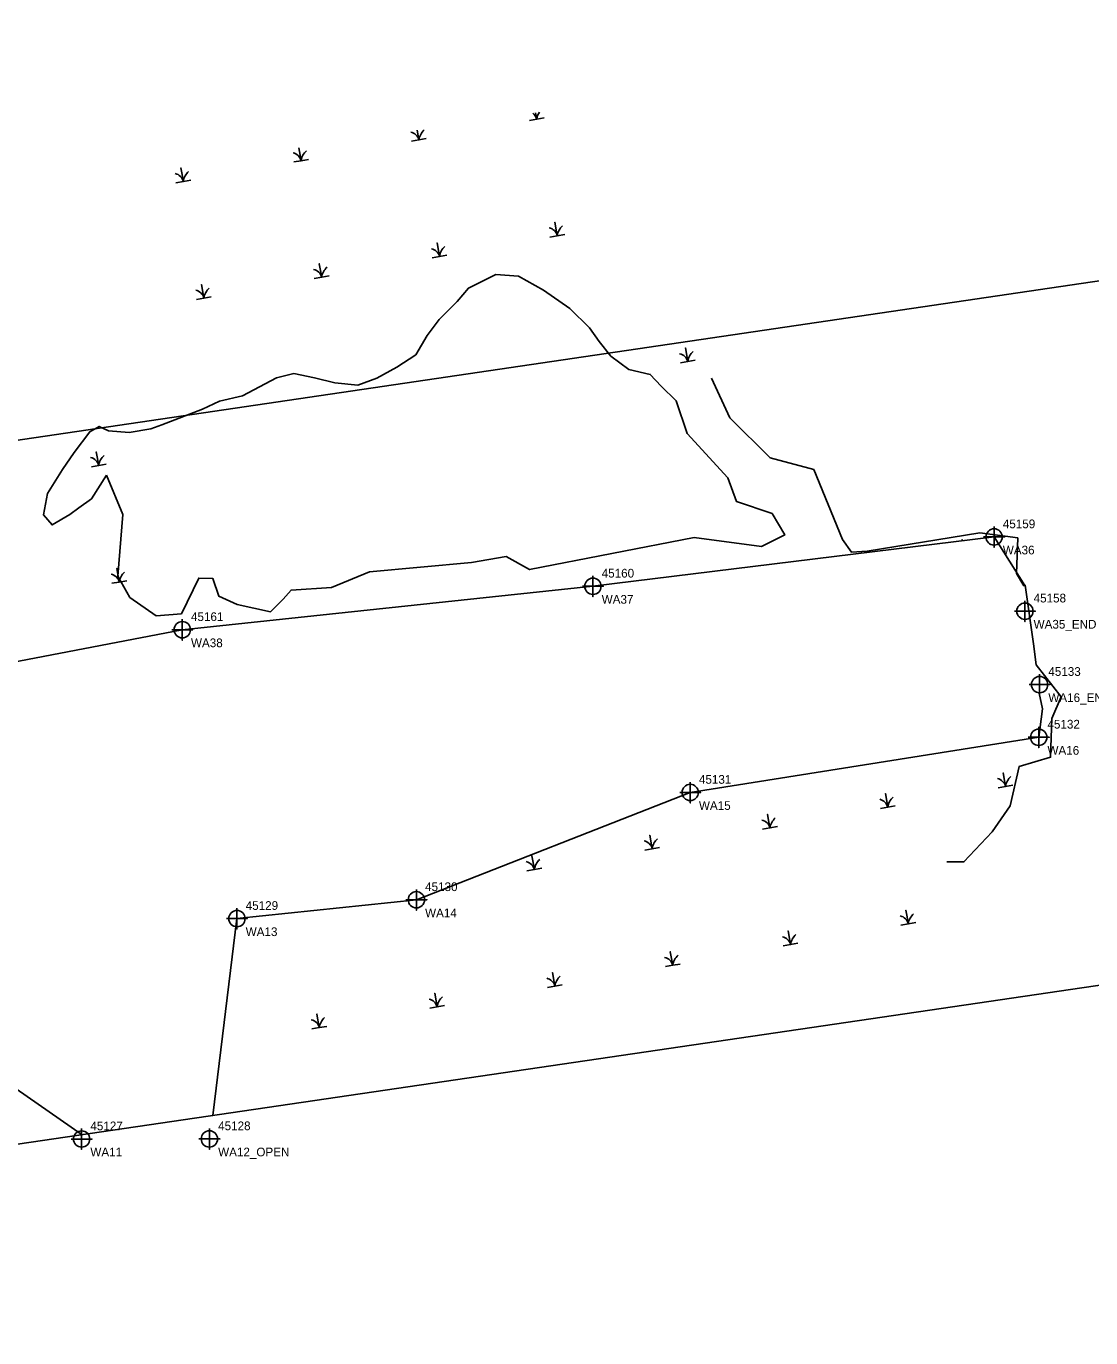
# Model space of a CAD drawing. Extents: x 2111078 to 2112839, y 581517 to 581907.
# Drawn here: x 2111765.7 to 2112071, y 581523.2 to 581899.2 of the extents above; entities that cross this region are included whole.
import ezdxf

# ---------------------------------------------------------------- set-up
doc = ezdxf.new("R2010")
doc.units = 0
for name, color, linetype in [('Default', 7, 'Continuous'), ('Exist Environmental Wetland Boundary', 7, 'Continuous'), ('Exist Environmental Wetland Boundary Cogo Comment', 7, 'Continuous'), ('Exist Environmental Wetland Boundary Cogo Number', 7, 'Continuous'), ('Exist Environmental Wetland Boundary Cogo Point CELL', 7, 'Continuous'), ('Exist Hydro Jurisdictional Stream or Body of Water Mitigable', 7, 'Continuous'), ('Exist Hydro Jurisdictional Stream or Body of Water NEU NonMitigable', 7, 'Continuous'), ('Exist Hydro Swamp or Marsh', 7, 'Continuous')]:
    doc.layers.add(name, color=color, linetype=linetype)

msp = doc.modelspace()

# ---------------------------------------------------------------- linework, layer by layer
at = {"layer": 'Default'}
msp.add_lwpolyline([(2111089.87, 581523.16), (2111077.52, 581722.78), (2111579.66, 581753.48), (2112568.99, 581899.18), (2112598.13, 581701.32), (2111600.4, 581554.74), (2111516.52, 581549.55)], close=True, dxfattribs=at)
at = {"layer": 'Exist Environmental Wetland Boundary'}
for points in [[(2112052.09, 581738.85), (2112043.26, 581752.76), (2111928.23, 581738.62), (2111810.46, 581726.15), (2111700.26, 581705.05), (2111584.01, 581692.46), (2111561.53, 581686.62), (2111561.94, 581674.72), (2111567.72, 581661.99), (2111570.98, 581641.26), (2111577.49, 581632.74), (2111580.7, 581632.54), (2111595.75, 581624.66), (2111698.44, 581639.38), (2111781.79, 581581.39)], [(2111819.27, 581586.89), (2111826.15, 581643.33), (2111877.59, 581648.73), (2111956.11, 581679.5), (2112056.05, 581695.32), (2112057.1, 581703.46), (2112056.2, 581707.94)]]:
    msp.add_lwpolyline(points, dxfattribs=at)
at = {"layer": 'Exist Environmental Wetland Boundary Cogo Point CELL'}
for points in [[(2112043.25, 581755.76), (2112043.25, 581749.76), (2112043.25, 581752.76), (2112046.25, 581752.76), (2112040.25, 581752.76)], [(2111928.23, 581741.62), (2111928.23, 581735.62), (2111928.23, 581738.62), (2111931.23, 581738.62), (2111925.23, 581738.62)], [(2112052.08, 581734.48), (2112052.08, 581728.48), (2112052.08, 581731.48), (2112055.08, 581731.48), (2112049.08, 581731.48)], [(2111810.46, 581729.15), (2111810.46, 581723.15), (2111810.46, 581726.15), (2111813.46, 581726.15), (2111807.46, 581726.15)], [(2112056.3, 581713.43), (2112056.3, 581707.43), (2112056.3, 581710.43), (2112059.3, 581710.43), (2112053.3, 581710.43)], [(2112056.05, 581698.32), (2112056.05, 581692.32), (2112056.05, 581695.32), (2112059.05, 581695.32), (2112053.05, 581695.32)], [(2111956.11, 581682.5), (2111956.11, 581676.5), (2111956.11, 581679.5), (2111959.11, 581679.5), (2111953.11, 581679.5)], [(2111877.59, 581651.73), (2111877.59, 581645.73), (2111877.59, 581648.73), (2111880.59, 581648.73), (2111874.59, 581648.73)], [(2111826.15, 581646.33), (2111826.15, 581640.33), (2111826.15, 581643.33), (2111829.15, 581643.33), (2111823.15, 581643.33)], [(2111781.61, 581583.15), (2111781.61, 581577.15), (2111781.61, 581580.15), (2111784.61, 581580.15), (2111778.61, 581580.15)], [(2111818.25, 581583.17), (2111818.25, 581577.17), (2111818.25, 581580.17), (2111821.25, 581580.17), (2111815.25, 581580.17)]]:
    msp.add_lwpolyline(points, dxfattribs=at)
for centre in [(2112043.25, 581752.76), (2111928.23, 581738.62), (2112052.08, 581731.48), (2111810.46, 581726.15), (2112056.3, 581710.43), (2112056.05, 581695.32), (2111956.11, 581679.5), (2111877.59, 581648.73), (2111826.15, 581643.33), (2111781.61, 581580.15), (2111818.25, 581580.17)]:
    msp.add_circle(centre, 2.34, dxfattribs=at)
at = {"layer": 'Exist Hydro Jurisdictional Stream or Body of Water Mitigable'}
for points in [[(2112059.84, 581700.7), (2112062.49, 581706.94), (2112055.34, 581716.13), (2112054.57, 581722.13), (2112052.17, 581738.93), (2112051.74, 581738.78), (2112049.7, 581742.29), (2112050.01, 581752.49), (2112039.14, 581753.92), (2112006.88, 581748.64), (2112002.32, 581748.44), (2111999.78, 581752.01), (2111991.54, 581772.1), (2111979.08, 581775.41), (2111967.43, 581786.95), (2111962.18, 581798.24)], [(2112029.69, 581659.66), (2112034.58, 581659.59), (2112042.72, 581668.18), (2112047.85, 581675.67), (2112050.4, 581686.92), (2112059.44, 581689.6), (2112059.84, 581700.7)]]:
    msp.add_lwpolyline(points, dxfattribs=at)
at = {"layer": 'Exist Hydro Jurisdictional Stream or Body of Water NEU NonMitigable'}
for points in [[(2111816.23, 581789.37), (2111821.14, 581791.65), (2111827.77, 581793.26), (2111837.5, 581798.42), (2111842.46, 581799.58), (2111848.36, 581798.34), (2111854.22, 581796.98), (2111860.81, 581796.24), (2111866.24, 581798.28), (2111871.96, 581801.48), (2111877.4, 581804.97), (2111880.65, 581810.55), (2111884.17, 581815.14), (2111889.33, 581820.24), (2111892.5, 581824.1), (2111900.42, 581828.05), (2111906.87, 581827.5), (2111914.07, 581823.55), (2111921.55, 581818.23), (2111927.23, 581812.73), (2111930.01, 581808.77), (2111933.39, 581804.55), (2111938.54, 581800.77), (2111944.65, 581799.37), (2111947.77, 581795.96), (2111952.05, 581791.74)], [(2111979.61, 581759.45), (2111969.35, 581762.93), (2111966.89, 581769.74), (2111955.28, 581782.43), (2111952.05, 581791.74)], [(2111788.78, 581770.51), (2111784.45, 581763.73), (2111780.82, 581761.11), (2111778.23, 581759.17), (2111773.15, 581756.2), (2111770.7, 581759.1), (2111771.85, 581765.17), (2111776.09, 581772.09), (2111779.45, 581776.96), (2111783.91, 581782.92), (2111786.65, 581784.46), (2111789.29, 581783.15), (2111795.25, 581782.73), (2111801.42, 581783.71), (2111804.58, 581784.93), (2111816.23, 581789.37)], [(2111788.78, 581770.51), (2111793.46, 581759.2), (2111791.95, 581741.53), (2111795.45, 581735.44), (2111802.97, 581730.1), (2111810.2, 581730.69), (2111815.18, 581740.97), (2111819.27, 581740.84), (2111820.95, 581735.75), (2111826.2, 581733.36), (2111835.8, 581731.32), (2111839.39, 581734.88), (2111841.65, 581737.52), (2111853.28, 581738.3), (2111864.19, 581742.8), (2111893.43, 581745.45), (2111903.31, 581747.12), (2111910.04, 581743.42), (2111957.26, 581752.56), (2111976.55, 581750.01)], [(2111979.61, 581759.45), (2111983.2, 581753.34), (2111976.55, 581750.01)]]:
    msp.add_lwpolyline(points, dxfattribs=at)
at = {"layer": 'Exist Hydro Swamp or Marsh'}
for points in [[(2111909.99, 581872.17), (2111912.11, 581872.55), (2111911.79, 581874.34)], [(2111911.79, 581874.34), (2111912.11, 581872.55), (2111914.22, 581872.92)], [(2111876.21, 581866.22), (2111878.33, 581866.59), (2111877.84, 581869.34)], [(2111877.84, 581869.34), (2111878.33, 581866.59), (2111880.44, 581866.96)], [(2111842.43, 581860.26), (2111844.55, 581860.63), (2111843.89, 581864.34)], [(2111843.89, 581864.34), (2111844.55, 581860.63), (2111846.66, 581861.01)], [(2111808.65, 581854.3), (2111810.77, 581854.68), (2111810.08, 581858.56), (2111810.77, 581854.68), (2111812.88, 581855.05)], [(2111915.88, 581838.74), (2111918, 581839.12), (2111917.31, 581843), (2111918, 581839.12), (2111920.12, 581839.49)], [(2111882.1, 581832.79), (2111884.22, 581833.16), (2111883.54, 581837.05), (2111884.22, 581833.16), (2111886.34, 581833.53)], [(2111848.32, 581826.83), (2111850.44, 581827.2), (2111849.76, 581831.09), (2111850.44, 581827.2), (2111852.56, 581827.58)], [(2111814.54, 581820.88), (2111816.66, 581821.25), (2111815.98, 581825.13), (2111816.66, 581821.25), (2111818.78, 581821.62)], [(2111953.29, 581802.68), (2111955.41, 581803.05), (2111954.72, 581806.94), (2111955.41, 581803.05), (2111957.52, 581803.42)], [(2111784.39, 581772.9), (2111786.51, 581773.27), (2111785.82, 581777.15), (2111786.51, 581773.27), (2111788.62, 581773.64)], [(2112034.13, 581751.64), (2112034.07, 581751.99), (2112034.13, 581751.64)], [(2111790.28, 581739.47), (2111792.4, 581739.84), (2111791.72, 581743.72), (2111792.4, 581739.84), (2111794.52, 581740.21)], [(2112044.43, 581680.87), (2112046.54, 581681.25), (2112045.86, 581685.13), (2112046.54, 581681.25), (2112048.66, 581681.62)], [(2112010.65, 581674.92), (2112012.76, 581675.29), (2112012.08, 581679.17), (2112012.76, 581675.29), (2112014.88, 581675.66)], [(2111976.87, 581668.96), (2111978.98, 581669.33), (2111978.3, 581673.22), (2111978.98, 581669.33), (2111981.1, 581669.71)], [(2111943.09, 581663), (2111945.2, 581663.38), (2111944.52, 581667.26), (2111945.2, 581663.38), (2111947.32, 581663.75)], [(2111909.31, 581657.05), (2111911.42, 581657.42), (2111910.74, 581661.31), (2111911.42, 581657.42), (2111913.54, 581657.79)], [(2112016.54, 581641.49), (2112018.66, 581641.86), (2112017.97, 581645.74), (2112018.66, 581641.86), (2112020.78, 581642.23)], [(2111982.76, 581635.53), (2111984.88, 581635.9), (2111984.19, 581639.79), (2111984.88, 581635.9), (2111987, 581636.28)], [(2111948.98, 581629.57), (2111951.1, 581629.95), (2111950.41, 581633.83), (2111951.1, 581629.95), (2111953.22, 581630.32)], [(2111915.2, 581623.62), (2111917.32, 581623.99), (2111916.63, 581627.88), (2111917.32, 581623.99), (2111919.44, 581624.36)], [(2111881.42, 581617.66), (2111883.54, 581618.03), (2111882.85, 581621.92), (2111883.54, 581618.03), (2111885.66, 581618.41)], [(2111847.64, 581611.7), (2111849.76, 581612.08), (2111849.07, 581615.96), (2111849.76, 581612.08), (2111851.88, 581612.45)]]:
    msp.add_lwpolyline(points, dxfattribs=at)
for centre, radius, start, end in [((2111909.12, 581871.8), 3.07, 14.1403, 52.2834), ((2111916.86, 581871.85), 4.81, 146.4858, 171.6222), ((2111875.34, 581865.84), 3.07, 14.1403, 77.535), ((2111883.08, 581865.89), 4.81, 132.1274, 171.6222), ((2111841.56, 581859.88), 3.07, 14.1403, 77.535), ((2111849.3, 581859.93), 4.81, 132.1274, 171.6222), ((2111815.52, 581853.98), 4.81, 132.1274, 171.6222), ((2111807.78, 581853.93), 3.07, 14.1403, 77.535), ((2111915.02, 581838.37), 3.07, 14.1403, 77.535), ((2111922.75, 581838.42), 4.81, 132.1274, 171.6222), ((2111881.24, 581832.41), 3.07, 14.1403, 77.535), ((2111888.97, 581832.46), 4.81, 132.1274, 171.6222), ((2111847.46, 581826.45), 3.07, 14.1403, 77.535), ((2111855.19, 581826.5), 4.81, 132.1274, 171.6222), ((2111813.68, 581820.5), 3.07, 14.1403, 77.535), ((2111821.42, 581820.55), 4.81, 132.1274, 171.6222), ((2111952.42, 581802.3), 3.07, 14.1403, 77.535), ((2111960.16, 581802.35), 4.81, 132.1274, 171.6222), ((2111783.53, 581772.52), 3.07, 14.1403, 77.535), ((2111791.26, 581772.57), 4.81, 132.1274, 171.6222), ((2111789.42, 581739.09), 3.07, 14.1403, 77.535), ((2111797.16, 581739.14), 4.81, 132.1274, 171.6222), ((2112043.56, 581680.49), 3.07, 14.1403, 77.535), ((2112051.3, 581680.54), 4.81, 132.1274, 171.6222), ((2112009.78, 581674.54), 3.07, 14.1403, 77.535), ((2112017.52, 581674.59), 4.81, 132.1274, 171.6222), ((2111976, 581668.58), 3.07, 14.1403, 77.535), ((2111983.74, 581668.63), 4.81, 132.1274, 171.6222), ((2111942.22, 581662.63), 3.07, 14.1403, 77.535), ((2111949.96, 581662.68), 4.81, 132.1274, 171.6222), ((2111908.44, 581656.67), 3.07, 14.1403, 77.535), ((2111916.18, 581656.72), 4.81, 132.1274, 171.6222), ((2112015.68, 581641.11), 3.07, 14.1403, 77.535), ((2112023.41, 581641.16), 4.81, 132.1274, 171.6222), ((2111981.9, 581635.15), 3.07, 14.1403, 77.535), ((2111989.63, 581635.2), 4.81, 132.1274, 171.6222), ((2111948.12, 581629.2), 3.07, 14.1403, 77.535), ((2111955.85, 581629.25), 4.81, 132.1274, 171.6222), ((2111914.34, 581623.24), 3.07, 14.1403, 77.535), ((2111922.07, 581623.29), 4.81, 132.1274, 171.6222), ((2111888.29, 581617.33), 4.81, 132.1274, 171.6222), ((2111880.56, 581617.28), 3.07, 14.1403, 77.535), ((2111846.78, 581611.33), 3.07, 14.1403, 77.535), ((2111854.51, 581611.38), 4.81, 132.1274, 171.6222)]:
    msp.add_arc(centre, radius, start, end, dxfattribs=at)

# ---------------------------------------------------------------- texts
at = {"layer": 'Exist Environmental Wetland Boundary Cogo Comment'}
for s, p in [('WA36', (2112045.75, 581747.76)), ('WA37', (2111930.73, 581733.62)), ('WA35_END BRIDGE', (2112054.58, 581726.48)), ('WA38', (2111812.96, 581721.15)), ('WA16_END OF BRIDGE', (2112058.8, 581705.43)), ('WA16', (2112058.55, 581690.32)), ('WA15', (2111958.61, 581674.5)), ('WA14', (2111880.09, 581643.73)), ('WA13', (2111828.65, 581638.33)), ('WA11', (2111784.11, 581575.15)), ('WA12_OPEN', (2111820.75, 581575.17))]:
    msp.add_text(s, height=2.5, dxfattribs=at).set_placement(p)
at = {"layer": 'Exist Environmental Wetland Boundary Cogo Number'}
for s, p in [('45159', (2112045.75, 581755.26)), ('45160', (2111930.73, 581741.12)), ('45158', (2112054.58, 581733.98)), ('45161', (2111812.96, 581728.65)), ('45133', (2112058.8, 581712.93)), ('45132', (2112058.55, 581697.82)), ('45131', (2111958.61, 581682)), ('45130', (2111880.09, 581651.23)), ('45129', (2111828.65, 581645.83)), ('45127', (2111784.11, 581582.65)), ('45128', (2111820.75, 581582.67))]:
    msp.add_text(s, height=2.5, dxfattribs=at).set_placement(p)

doc.saveas('drawing.dxf')
